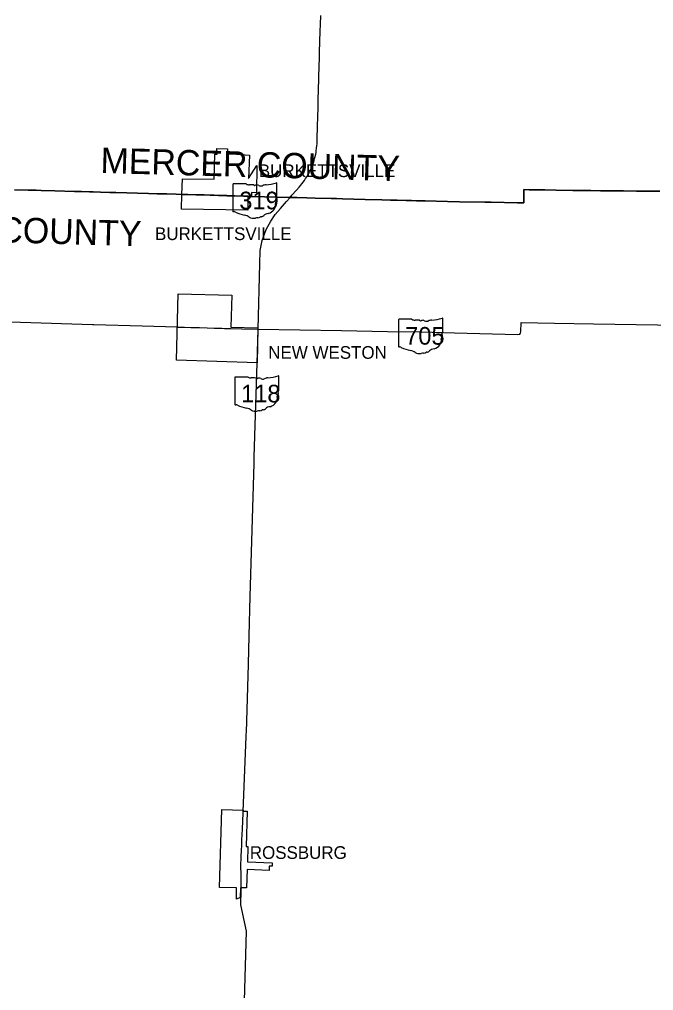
# Model space of a CAD drawing. Extents: x 0 to 34, y 0 to 22.
# Drawn here: x 3.218 to 3.621, y 18.175 to 18.791 of the extents above; entities that cross this region are included whole.
import ezdxf

# ---------------------------------------------------------------- set-up
doc = ezdxf.new("R2010")
doc.units = 0
for name, color, linetype in [('GM_X_Corporation', 7, 'Continuous'), ('GM_X_Corporation_Text', 7, 'Continuous'), ('GM_X_County', 7, 'Continuous'), ('GM_X_County_Text', 7, 'Continuous'), ('GM_X_State_Location', 7, 'Continuous'), ('GM_X_State_Route', 7, 'Continuous'), ('GM_X_State_Shield', 7, 'Continuous')]:
    doc.layers.add(name, color=color, linetype=linetype)

msp = doc.modelspace()

# ---------------------------------------------------------------- linework, layer by layer
at = {"layer": 'GM_X_Corporation'}
for points in [[(3.3214, 18.67964), (3.32174, 18.68947), (3.34176, 18.6893), (3.3422, 18.70517), (3.34375, 18.70514), (3.34352, 18.70606), (3.34344, 18.70682), (3.34345, 18.70872), (3.35032, 18.70855), (3.35024, 18.70539), (3.35336, 18.70536), (3.36429, 18.70449), (3.36368, 18.68973), (3.36899, 18.69791), (3.36869, 18.68061), (3.36548, 18.68073), (3.36543, 18.67832), (3.36322, 18.67839), (3.36322, 18.66955), (3.32103, 18.67022)], [(3.31786, 18.57441), (3.31901, 18.6166), (3.353, 18.61568), (3.35245, 18.59546), (3.36963, 18.595), (3.36902, 18.57279)], [(3.34515, 18.23988), (3.34676, 18.28944), (3.36024, 18.289), (3.36022, 18.28841), (3.36281, 18.28832), (3.36208, 18.26589), (3.36325, 18.26585), (3.36293, 18.25617), (3.3787, 18.25565), (3.37863, 18.25342), (3.37679, 18.25348), (3.3767, 18.25079), (3.36273, 18.25125), (3.36235, 18.23976), (3.35855, 18.2398), (3.35838, 18.2335), (3.35596, 18.23254), (3.35595, 18.23969)]]:
    msp.add_lwpolyline(points, close=True, dxfattribs=at)
at = {"layer": 'GM_X_County'}
for points in [[(3.62466, 18.68161), (3.61981, 18.68166), (3.60984, 18.68176), (3.60161, 18.68182), (3.59497, 18.6819), (3.5869, 18.68194), (3.58073, 18.68202), (3.56939, 18.68217), (3.55879, 18.68234), (3.55162, 18.68242), (3.54423, 18.68253), (3.54175, 18.68259), (3.53831, 18.68263), (3.53829, 18.68106), (3.53835, 18.67553), (3.53833, 18.67424), (3.53753, 18.67426), (3.53421, 18.6743), (3.5176, 18.67462), (3.51364, 18.67469), (3.49756, 18.67499), (3.48981, 18.67517), (3.47568, 18.67552), (3.4749, 18.67553), (3.47431, 18.67553), (3.4704, 18.67561), (3.47021, 18.67561), (3.46713, 18.67566), (3.46371, 18.67575), (3.45785, 18.67589), (3.45364, 18.676), (3.44821, 18.67614), (3.43761, 18.67643), (3.42327, 18.6768), (3.41937, 18.67691), (3.4161, 18.67698), (3.40587, 18.67724), (3.40065, 18.67739), (3.39432, 18.67756), (3.39002, 18.67769), (3.36543, 18.67832), (3.36322, 18.67839), (3.35489, 18.67869), (3.34989, 18.67882), (3.34624, 18.67892), (3.34464, 18.67897), (3.34189, 18.67906), (3.34037, 18.6791), (3.33939, 18.67913), (3.33554, 18.67924), (3.33144, 18.67935), (3.33016, 18.67939), (3.32507, 18.67953), (3.3214, 18.67964), (3.31768, 18.67973), (3.31182, 18.67988), (3.3056, 18.68007), (3.30016, 18.68023), (3.27943, 18.68082), (3.27558, 18.68092), (3.26983, 18.68109), (3.26514, 18.68122), (3.26282, 18.68129), (3.25763, 18.68143), (3.25318, 18.68155), (3.24074, 18.68188), (3.23215, 18.68213), (3.22893, 18.68223), (3.22646, 18.68228), (3.22387, 18.68233), (3.21511, 18.68259)], [(3.21511, 18.68259), (3.22387, 18.68233), (3.22646, 18.68228), (3.22893, 18.68223), (3.23215, 18.68213), (3.24074, 18.68188), (3.25318, 18.68155), (3.25763, 18.68143), (3.26282, 18.68129), (3.26514, 18.68122), (3.26983, 18.68109), (3.27558, 18.68092), (3.27943, 18.68082), (3.30016, 18.68023), (3.3056, 18.68007), (3.31182, 18.67988), (3.31768, 18.67973), (3.3214, 18.67964), (3.32507, 18.67953), (3.33016, 18.67939), (3.33144, 18.67935), (3.33554, 18.67924), (3.33939, 18.67913), (3.34037, 18.6791), (3.34189, 18.67906), (3.34464, 18.67897), (3.34624, 18.67892), (3.34989, 18.67882), (3.35489, 18.67869), (3.36322, 18.67839), (3.36543, 18.67832), (3.39002, 18.67769), (3.39432, 18.67756), (3.40065, 18.67739), (3.40587, 18.67724), (3.4161, 18.67698), (3.41937, 18.67691), (3.42327, 18.6768), (3.43761, 18.67643), (3.44821, 18.67614), (3.45364, 18.676), (3.45785, 18.67589), (3.46371, 18.67575), (3.46713, 18.67566), (3.47021, 18.67561), (3.4704, 18.67561), (3.47431, 18.67553), (3.4749, 18.67553), (3.47568, 18.67552), (3.48981, 18.67517), (3.49756, 18.67499), (3.51364, 18.67469), (3.5176, 18.67462), (3.53421, 18.6743), (3.53753, 18.67426), (3.53833, 18.67424), (3.53835, 18.67553), (3.53829, 18.68106), (3.53831, 18.68263), (3.54175, 18.68259), (3.54423, 18.68253), (3.55162, 18.68242), (3.55879, 18.68234), (3.56939, 18.68217), (3.58073, 18.68202), (3.5869, 18.68194), (3.59497, 18.6819), (3.60161, 18.68182), (3.60984, 18.68176), (3.61981, 18.68166), (3.62466, 18.68161)]]:
    msp.add_lwpolyline(points, dxfattribs=at)
at = {"layer": 'GM_X_State_Route'}
for p, q in [((3.35571, 18.67862), (3.36052, 18.67845)), ((3.36609, 18.67825), (3.36769, 18.67821)), ((3.36769, 18.67821), (3.39005, 18.67765)), ((3.35951, 18.5943), (3.36968, 18.59401)), ((3.36904, 18.57254), (3.36968, 18.59401)), ((3.36729, 18.51308), (3.36904, 18.57254))]:
    msp.add_line(p, q, dxfattribs=at)
for points in [[(3.4072, 18.7125), (3.40722, 18.713), (3.40726, 18.71392), (3.40729, 18.71484), (3.40745, 18.72259), (3.40761, 18.72908), (3.40779, 18.7344), (3.40791, 18.73967), (3.40825, 18.7528), (3.40852, 18.76213), (3.4086, 18.76503), (3.40873, 18.76993), (3.40914, 18.78316), (3.40927, 18.78743), (3.40943, 18.79307)], [(3.39005, 18.67765), (3.39122, 18.67909), (3.3941, 18.68232), (3.39581, 18.68426), (3.39676, 18.68538), (3.39749, 18.68629), (3.39826, 18.6873), (3.39906, 18.68841), (3.39985, 18.6896), (3.40058, 18.69076), (3.40128, 18.69195), (3.40182, 18.69292), (3.4024, 18.69404), (3.40308, 18.69547), (3.40368, 18.69683), (3.40421, 18.69815), (3.40478, 18.69974), (3.40522, 18.7011), (3.40559, 18.70242), (3.40593, 18.70375), (3.40625, 18.70514), (3.40646, 18.70623), (3.40665, 18.70733), (3.40687, 18.70889), (3.40704, 18.71036), (3.40715, 18.71168), (3.4072, 18.7125)], [(3.34466, 18.67892), (3.34626, 18.67888), (3.34991, 18.67877), (3.35491, 18.67865), (3.35571, 18.67862)], [(3.36052, 18.67845), (3.36324, 18.67835), (3.36545, 18.67827), (3.36609, 18.67825)], [(3.36968, 18.59401), (3.37085, 18.63548), (3.37109, 18.64402), (3.37225, 18.65027), (3.37484, 18.65739), (3.37775, 18.66267), (3.3805, 18.66688), (3.38386, 18.6707), (3.38781, 18.67505), (3.39005, 18.67765)], [(3.0541, 18.60308), (3.11528, 18.60161), (3.1578, 18.60032), (3.20074, 18.59902), (3.21888, 18.59846), (3.26465, 18.59705), (3.2655, 18.59703), (3.29624, 18.59614), (3.31844, 18.5955), (3.31887, 18.59548)], [(3.31887, 18.59548), (3.32295, 18.59536), (3.32698, 18.59525), (3.32732, 18.59524)], [(3.32732, 18.59524), (3.32792, 18.59522), (3.33263, 18.59508), (3.33749, 18.59494), (3.34189, 18.59481), (3.3468, 18.59467), (3.34833, 18.59463), (3.3485, 18.59462)], [(3.3485, 18.59462), (3.35243, 18.59451), (3.35943, 18.5943), (3.35951, 18.5943)], [(3.36968, 18.59401), (3.42267, 18.59322), (3.45186, 18.5927), (3.47309, 18.59233)], [(3.47309, 18.59233), (3.49425, 18.59176), (3.53449, 18.59069), (3.53572, 18.59095), (3.53626, 18.59167), (3.53631, 18.59245), (3.5366, 18.59827), (3.55784, 18.59794), (3.58258, 18.59756), (3.62317, 18.59694), (3.65963, 18.5964)], [(3.36405, 18.39963), (3.36476, 18.42458), (3.36717, 18.50895), (3.36729, 18.51308)], [(3.36216, 18.3358), (3.36223, 18.33747), (3.36226, 18.33832), (3.36353, 18.38157), (3.36405, 18.39963)], [(3.36019, 18.28738), (3.36022, 18.28804), (3.36216, 18.3358)], [(3.35948, 18.26981), (3.35948, 18.26989), (3.35949, 18.27015), (3.35977, 18.27697), (3.36019, 18.28738)], [(3.359, 18.24273), (3.359, 18.24299), (3.359, 18.24819), (3.35881, 18.25342), (3.35883, 18.25397), (3.35903, 18.2589), (3.35925, 18.2643), (3.35932, 18.26589), (3.35948, 18.26981)], [(3.35897, 18.23844), (3.35897, 18.23878), (3.359, 18.24056), (3.359, 18.24273)], [(3.36115, 18.1681), (3.36243, 18.21229), (3.35883, 18.22897), (3.35897, 18.23844)]]:
    msp.add_lwpolyline(points, dxfattribs=at)
at = {"layer": 'GM_X_State_Shield'}
for p, q in [((3.36217, 18.68623), (3.35398, 18.68623)), ((3.38168, 18.67776), (3.38168, 18.68665)), ((3.35371, 18.68594), (3.35371, 18.66895)), ((3.38168, 18.67777), (3.38168, 18.67776)), ((3.45887, 18.60008), (3.45887, 18.58309)), ((3.46734, 18.60037), (3.45915, 18.60037)), ((3.48685, 18.5919), (3.48685, 18.60079)), ((3.48684, 18.59191), (3.48685, 18.5919)), ((3.35491, 18.56344), (3.35491, 18.54646)), ((3.36338, 18.56373), (3.35518, 18.56373)), ((3.38288, 18.55527), (3.38288, 18.56415)), ((3.38288, 18.55527), (3.38288, 18.55527))]:
    msp.add_line(p, q, dxfattribs=at)
for centre, major_axis, start_param, end_param in [((3.35403, 18.68597), (0.000324, 0), 1.712693, 3.28349), ((3.36412, 18.6882), (0.00314, 0), 4.042523, 4.731795), ((3.37171, 18.70938), (0.02966, 0), 4.814394, 5.042369), ((3.38137, 18.68669), (0.000311, 0), 6.141152, 7.989035), ((3.36517, 18.67669), (0.01128, 0), 1.404758, 1.657858), ((3.36773, 18.68606), (0.000907, 0), 3.836095, 5.185415), ((3.36906, 18.6841), (0.00189, 0), 0.950623, 2.079405), ((3.37149, 18.68679), (0.00227, 0), 4.081561, 5.145723), ((3.3755, 18.68104), (0.00597, 0), 1.699011, 2.107814), ((3.37338, 18.67292), (0.00742, 0), 5.101752, 6.440018), ((3.38279, 18.67405), (0.0021, 0), 2.387724, 3.262537), ((3.38161, 18.67711), (0.000482, 0), 1.883978, 3.671073), ((3.37854, 18.67599), (0.00289, 0), 5.934695, 6.695948), ((3.38135, 18.67773), (0.000333, 0), 5.05454, 6.418171), ((3.35403, 18.66891), (0.000327, 0), 3.00124, 4.508301), ((3.35408, 18.67065), (0.00249, 0), 4.665946, 4.897461), ((3.35459, 18.66797), (0.0009, 0), 0.519207, 1.627899), ((3.36595, 18.68323), (0.02142, 0), 4.195997, 4.488961), ((3.35956, 18.66132), (0.0067, 0), 0.823519, 1.323587), ((3.36681, 18.66789), (0.00425, 0), 4.026481, 4.996735), ((3.36927, 18.66202), (0.00349, 0), 1.495662, 1.94098), ((3.36958, 18.66662), (0.00227, 0), 4.691044, 5.507374), ((3.37163, 18.66497), (0.000638, 0), 1.147584, 2.315152), ((3.37136, 18.66731), (0.0024, 0), 4.937069, 5.64225), ((3.3765, 18.66418), (0.00406, 0), 1.647645, 2.488434), ((3.4592, 18.60011), (0.000324, 0), 1.712693, 3.28349), ((3.46929, 18.60234), (0.00314, 0), 4.042523, 4.731795), ((3.47033, 18.59083), (0.01128, 0), 1.404758, 1.657858), ((3.47423, 18.59824), (0.00189, 0), 0.950623, 2.079405), ((3.48067, 18.59518), (0.00597, 0), 1.699011, 2.107814), ((3.47688, 18.62352), (0.02966, 0), 4.814394, 5.042369), ((3.48654, 18.60083), (0.000311, 0), 6.141152, 7.989035), ((3.4729, 18.6002), (0.000907, 0), 3.836095, 5.185415), ((3.47666, 18.60093), (0.00227, 0), 4.081561, 5.145723), ((3.47854, 18.58706), (0.00742, 0), 5.101752, 6.440018), ((3.48796, 18.58819), (0.0021, 0), 2.387724, 3.262537), ((3.48677, 18.59125), (0.000482, 0), 1.883978, 3.671073), ((3.48371, 18.59013), (0.00289, 0), 5.934695, 6.695948), ((3.48651, 18.59187), (0.000333, 0), 5.05454, 6.418171), ((3.4592, 18.58305), (0.000327, 0), 3.00124, 4.508301), ((3.45925, 18.58479), (0.00249, 0), 4.665946, 4.897461), ((3.45976, 18.58211), (0.0009, 0), 0.519207, 1.627899), ((3.47112, 18.59737), (0.02142, 0), 4.195997, 4.488961), ((3.48167, 18.57832), (0.00406, 0), 1.647645, 2.488434), ((3.46473, 18.57546), (0.0067, 0), 0.823519, 1.323587), ((3.47198, 18.58203), (0.00425, 0), 4.026481, 4.996735), ((3.47444, 18.57615), (0.00349, 0), 1.495662, 1.94098), ((3.47475, 18.58075), (0.00227, 0), 4.691044, 5.507374), ((3.4768, 18.57911), (0.000638, 0), 1.147584, 2.315152), ((3.47652, 18.58144), (0.0024, 0), 4.937069, 5.64225), ((3.35523, 18.56348), (0.000324, 0), 1.712693, 3.28349), ((3.36533, 18.5657), (0.00314, 0), 4.042523, 4.731795), ((3.36637, 18.5542), (0.01128, 0), 1.404758, 1.657858), ((3.36893, 18.56356), (0.000907, 0), 3.836095, 5.185415), ((3.37026, 18.5616), (0.00189, 0), 0.950623, 2.079405), ((3.3767, 18.55854), (0.00597, 0), 1.699011, 2.107814), ((3.37292, 18.58689), (0.02966, 0), 4.814394, 5.042369), ((3.38257, 18.56419), (0.000311, 0), 6.141152, 7.989035), ((3.37269, 18.56429), (0.00227, 0), 4.081561, 5.145723), ((3.37458, 18.55042), (0.00742, 0), 5.101752, 6.440018), ((3.384, 18.55155), (0.0021, 0), 2.387724, 3.262537), ((3.38281, 18.55462), (0.000482, 0), 1.883978, 3.671073), ((3.37974, 18.55349), (0.00289, 0), 5.934695, 6.695948), ((3.38255, 18.55523), (0.000333, 0), 5.05454, 6.418171), ((3.35523, 18.54642), (0.000327, 0), 3.00124, 4.508301), ((3.35528, 18.54816), (0.00249, 0), 4.665946, 4.897461), ((3.35579, 18.54548), (0.0009, 0), 0.519207, 1.627899), ((3.36715, 18.56074), (0.02142, 0), 4.195997, 4.488961), ((3.37771, 18.54169), (0.00406, 0), 1.647645, 2.488434), ((3.36076, 18.53882), (0.0067, 0), 0.823519, 1.323587), ((3.36801, 18.54539), (0.00425, 0), 4.026481, 4.996735), ((3.37047, 18.53952), (0.00349, 0), 1.495662, 1.94098), ((3.37078, 18.54412), (0.00227, 0), 4.691044, 5.507374), ((3.37283, 18.54247), (0.000638, 0), 1.147584, 2.315152), ((3.37256, 18.54481), (0.0024, 0), 4.937069, 5.64225)]:
    msp.add_ellipse(centre, major_axis=major_axis, ratio=0.8, start_param=start_param, end_param=end_param, dxfattribs=at)

# ---------------------------------------------------------------- texts
at = {"layer": 'GM_X_Corporation_Text'}
for s, p in [('BURKETTSVILLE', (3.37018, 18.69059)), ('BURKETTSVILLE', (3.30431, 18.65063)), ('NEW WESTON', (3.37616, 18.57531)), ('ROSSBURG', (3.36446, 18.25806))]:
    msp.add_text(s, height=0.008037, rotation=0.00001, dxfattribs=at).set_placement(p)
at = {"layer": 'GM_X_County_Text'}
for s, rotation, p in [('MERCER COUNTY', 358.42964, (3.26961, 18.69321)), ('DARKE COUNTY', 358.27225, (3.12475, 18.65174))]:
    msp.add_text(s, height=0.016074, rotation=rotation, dxfattribs=at).set_placement(p)
at = {"layer": 'GM_X_State_Location'}
for s, p in [('319', (3.3617, 18.67515)), ('705', (3.46687, 18.58928)), ('118', (3.36291, 18.55265))]:
    msp.add_text(s, height=0.0000161, rotation=0.00001, dxfattribs=at).set_placement(p)
for s, p in [('s', (3.36738, 18.67631)), ('r', (3.36738, 18.67631)), ('s', (3.47255, 18.59045)), ('r', (3.47255, 18.59045)), ('s', (3.36858, 18.55382)), ('r', (3.36858, 18.55382))]:
    msp.add_text(s, height=0.0000161, dxfattribs=at).set_placement(p)
at = {"layer": 'GM_X_State_Shield'}
for s, p in [('319', (3.35782, 18.67015)), ('705', (3.46304, 18.58429)), ('118', (3.35895, 18.54765))]:
    msp.add_text(s, height=0.011189, dxfattribs=at).set_placement(p)

doc.saveas('drawing.dxf')
